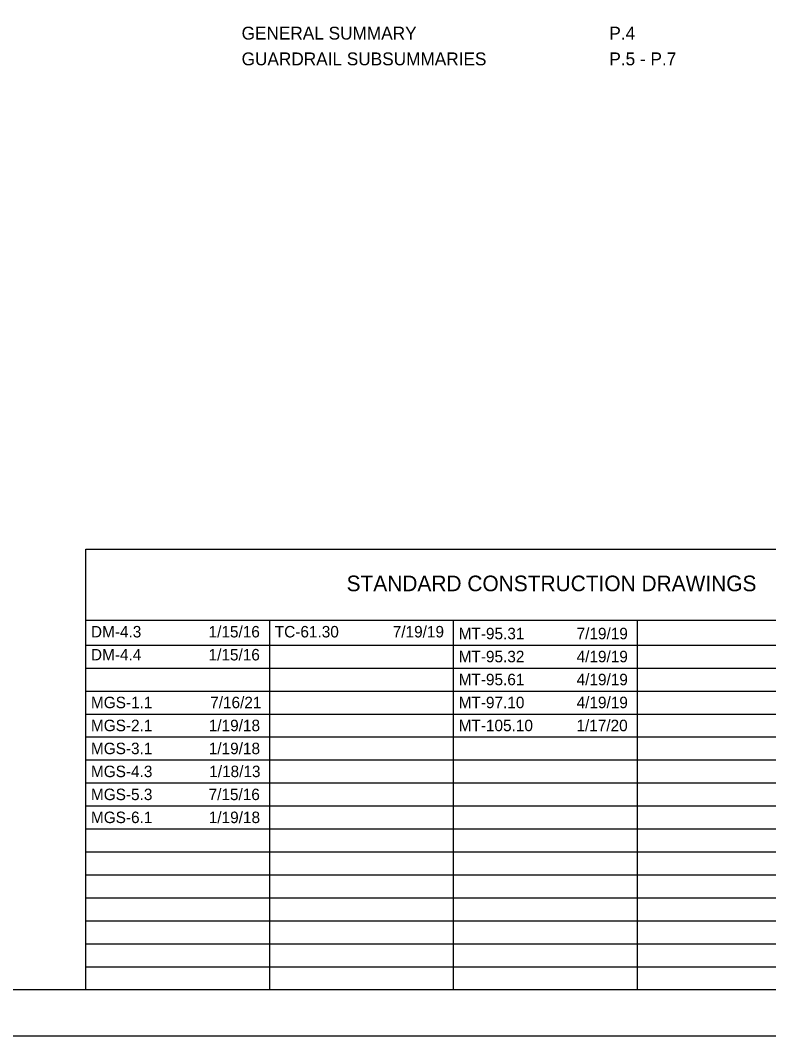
# Model space of a CAD drawing. Extents: x -8 to 42.1, y -22 to 0.
# Drawn here: x 9.44 to 17.58, y -22 to -10.95 of the extents above; entities that cross this region are included whole.
import ezdxf

# ---------------------------------------------------------------- set-up
doc = ezdxf.new("R2010")
doc.units = 0
for name, color, linetype in [('SH_Border', 7, 'Continuous'), ('SH_Cut_Line', 7, 'Continuous'), ('SH_Data', 7, 'Continuous'), ('SH_Text', 7, 'Continuous')]:
    doc.layers.add(name, color=color, linetype=linetype)

msp = doc.modelspace()

# ---------------------------------------------------------------- linework, layer by layer
at = {"layer": 'SH_Border'}
msp.add_lwpolyline([(1.5, -0.5), (33.5, -0.5), (33.5, -21.5), (1.5, -21.5)], close=True, dxfattribs=at)
at = {"layer": 'SH_Cut_Line'}
msp.add_lwpolyline([(0, -22), (34, -22), (34, 0), (0, 0)], close=True, dxfattribs=at)
at = {"layer": 'SH_Data'}
for p, q in [((10.15, -16.708), (23.6, -16.708)), ((10.15, -21.5), (10.15, -16.708)), ((10.15, -17.479), (23.6, -17.479)), ((12.15, -21.5), (12.15, -17.479)), ((14.15, -21.5), (14.15, -17.479)), ((16.15, -21.5), (16.15, -17.479)), ((10.15, -17.75), (23.6, -17.75)), ((10.15, -18), (23.6, -18)), ((10.15, -18.25), (23.6, -18.25)), ((10.15, -18.5), (23.6, -18.5)), ((10.15, -18.75), (23.6, -18.75)), ((10.15, -19), (23.6, -19)), ((10.15, -19.25), (23.6, -19.25)), ((10.15, -19.5), (23.6, -19.5)), ((10.15, -19.75), (23.6, -19.75)), ((10.15, -20), (23.6, -20)), ((10.15, -20.25), (23.6, -20.25)), ((10.15, -20.5), (23.6, -20.5)), ((10.15, -20.75), (23.6, -20.75)), ((10.15, -21), (23.6, -21)), ((10.15, -21.25), (23.6, -21.25))]:
    msp.add_line(p, q, dxfattribs=at)

# ---------------------------------------------------------------- texts
at = {"layer": 'SH_Text'}
for s, height, p in [('GENERAL SUMMARY', 0.14, (11.844, -11.162)), ('P.4', 0.14, (15.844, -11.162)), ('GUARDRAIL SUBSUMMARIES', 0.14, (11.844, -11.442)), ('P.5 - P.7', 0.14, (15.844, -11.442)), ('STANDARD CONSTRUCTION DRAWINGS', 0.17, (12.986, -17.164)), ('DM-4.3', 0.125, (10.205, -17.667)), ('1/15/16', 0.125, (11.485, -17.667)), ('TC-61.30', 0.125, (12.205, -17.667)), ('7/19/19', 0.125, (13.488, -17.667)), ('MT-95.31', 0.125, (14.205, -17.687)), ('7/19/19', 0.125, (15.488, -17.687)), ('1/15/16', 0.125, (11.485, -17.917)), ('DM-4.4', 0.125, (10.205, -17.917)), ('MT-95.32', 0.125, (14.205, -17.937)), ('4/19/19', 0.125, (15.488, -17.937)), ('MT-95.61', 0.125, (14.205, -18.187)), ('4/19/19', 0.125, (15.488, -18.187)), ('MGS-1.1', 0.125, (10.205, -18.437)), ('7/16/21', 0.125, (11.502, -18.437)), ('MT-97.10', 0.125, (14.205, -18.437)), ('4/19/19', 0.125, (15.488, -18.437)), ('1/19/18', 0.125, (11.487, -18.687)), ('1/17/20', 0.125, (15.486, -18.687)), ('MGS-2.1', 0.125, (10.205, -18.687)), ('MT-105.10', 0.125, (14.205, -18.687)), ('MGS-3.1', 0.125, (10.205, -18.937)), ('1/19/18', 0.125, (11.487, -18.937)), ('MGS-4.3', 0.125, (10.205, -19.187)), ('1/18/13', 0.125, (11.492, -19.187)), ('MGS-5.3', 0.125, (10.205, -19.437)), ('7/15/16', 0.125, (11.485, -19.437)), ('MGS-6.1', 0.125, (10.205, -19.687)), ('1/19/18', 0.125, (11.487, -19.687))]:
    msp.add_text(s, height=height, dxfattribs=at).set_placement(p)

doc.saveas('drawing.dxf')
